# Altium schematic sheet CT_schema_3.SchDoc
size 372 x 317 mm
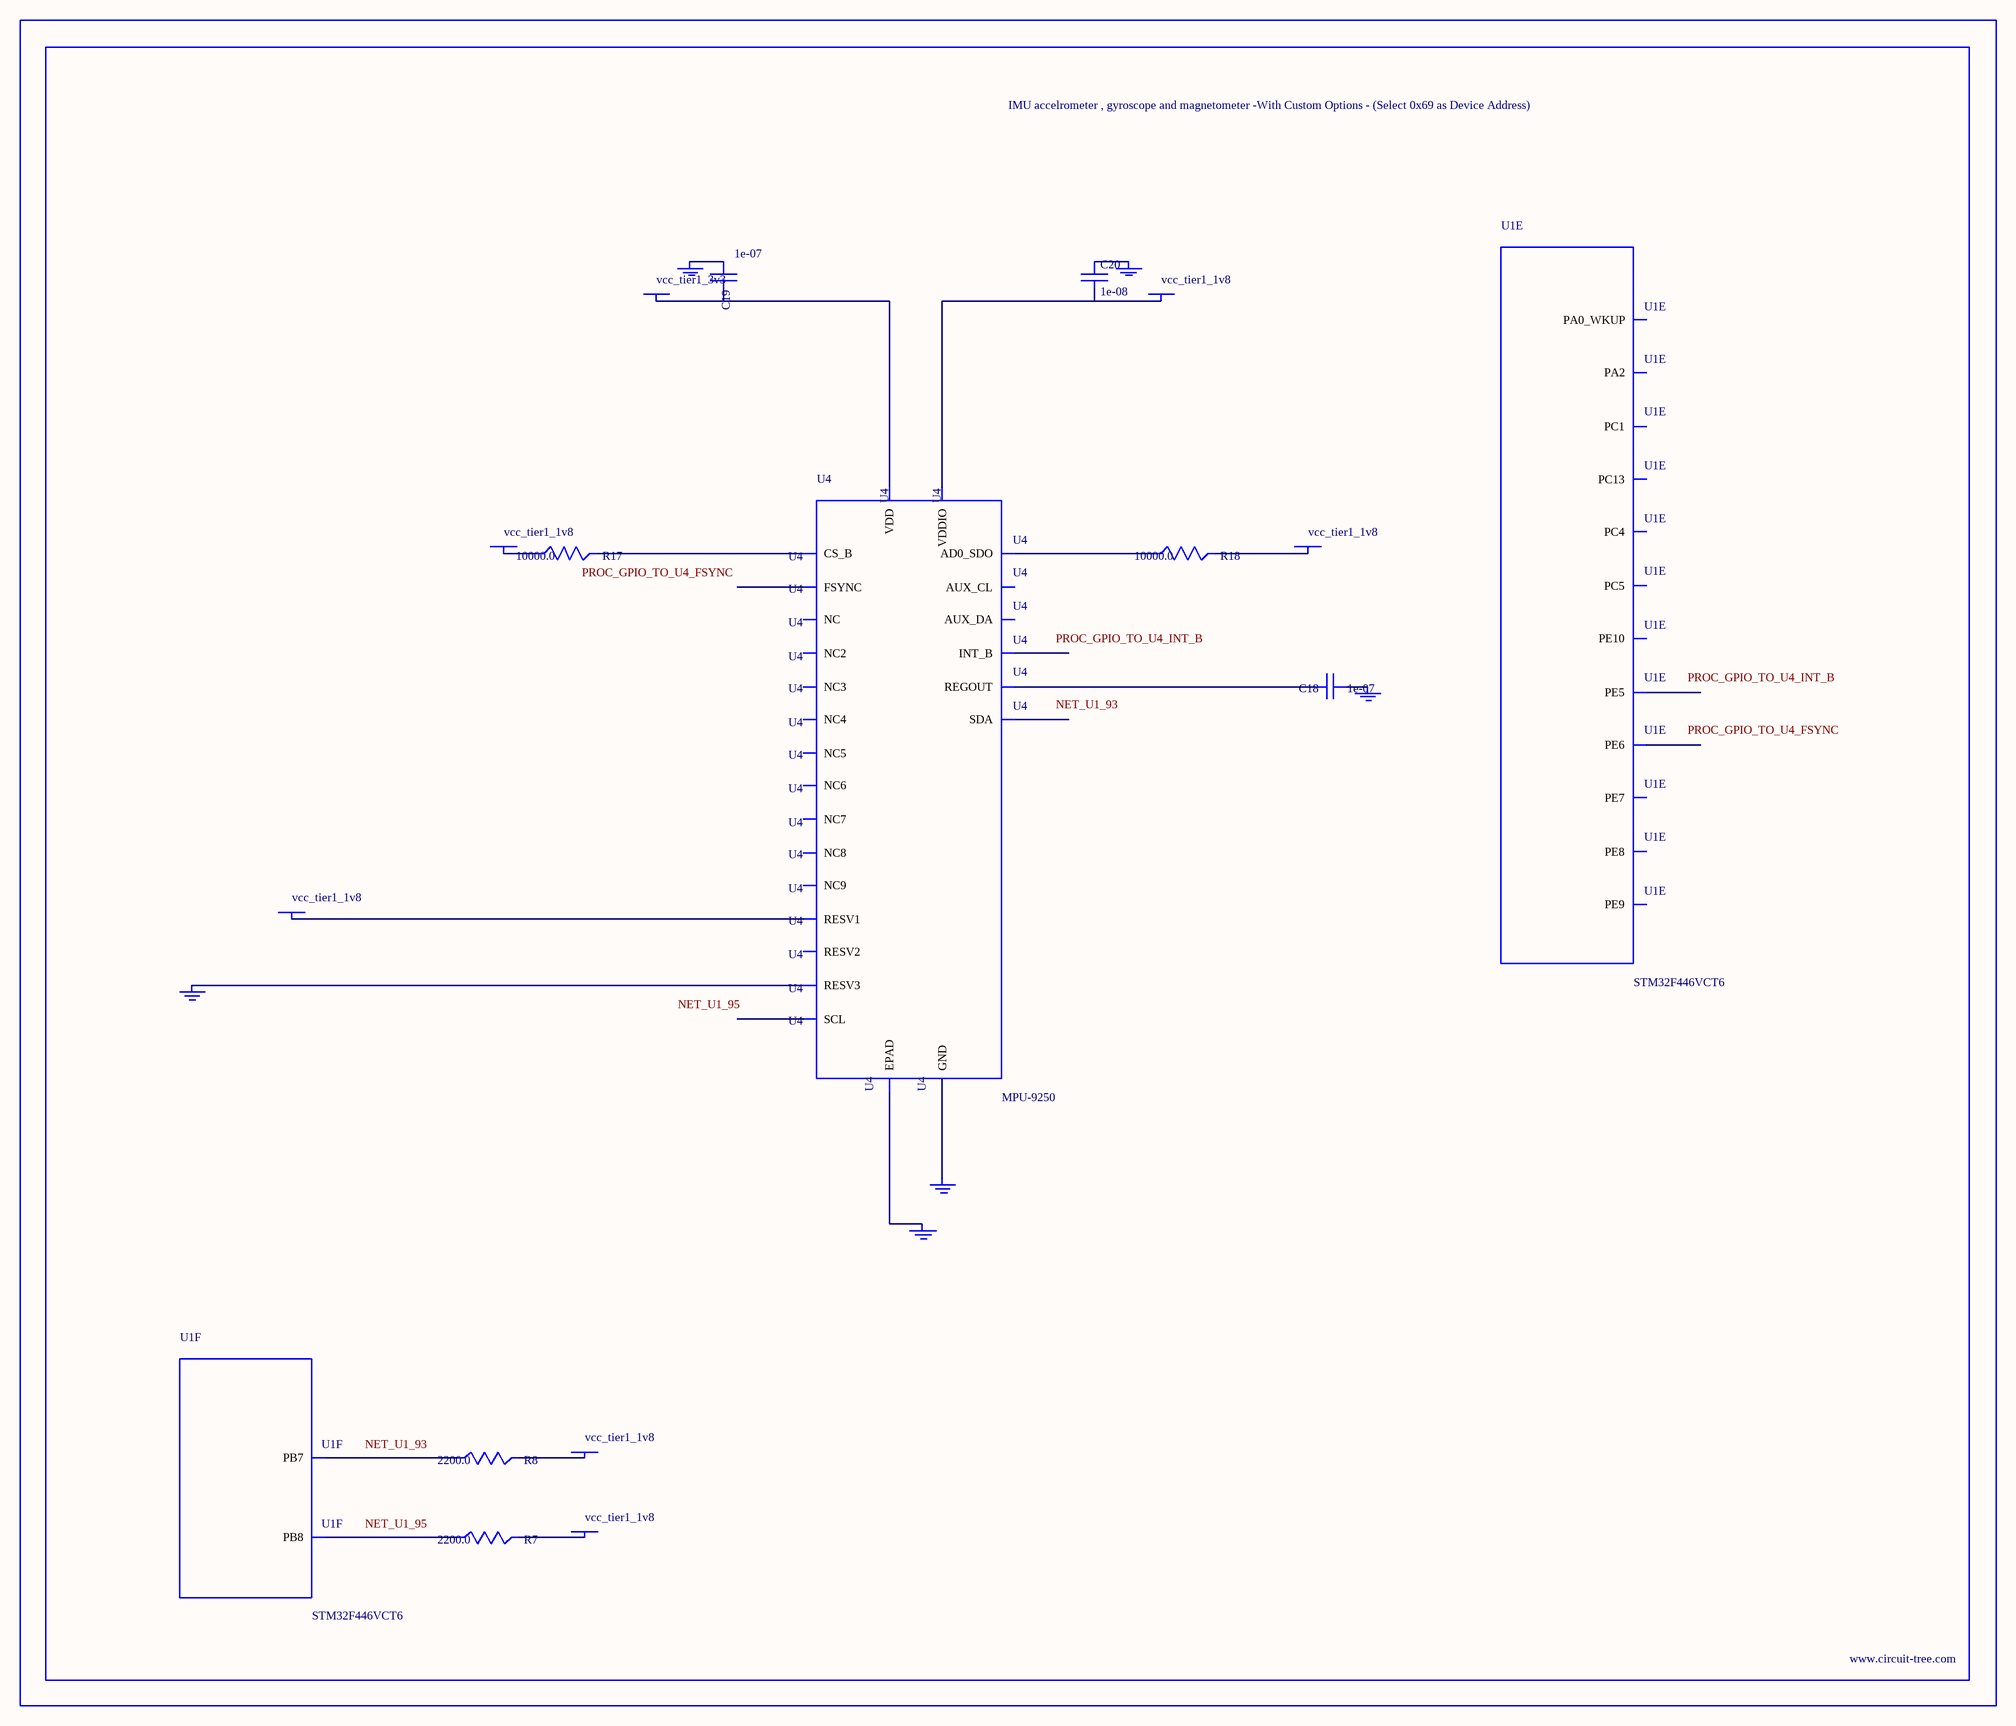
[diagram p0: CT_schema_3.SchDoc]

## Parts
BORDER2  (no value)
C18  1e-07  [C0402]
C19  1e-07  [C0402]
C20  1e-08  [C0402]
GND_INSTANCE_2_0  (no value)
GND_INSTANCE_2_1  (no value)
GND_INSTANCE_2_2  (no value)
GND_INSTANCE_2_3  (no value)
GND_INSTANCE_2_4  (no value)
GND_INSTANCE_2_5  (no value)
POWER_INSTANCE_2_0  vcc_tier1_1v8
POWER_INSTANCE_2_1  vcc_tier1_1v8
POWER_INSTANCE_2_2  vcc_tier1_1v8
POWER_INSTANCE_2_3  vcc_tier1_3v3
POWER_INSTANCE_2_4  vcc_tier1_1v8
POWER_INSTANCE_2_5  vcc_tier1_1v8
POWER_INSTANCE_2_6  vcc_tier1_1v8
R7  2200.0  [R0603]
R8  2200.0  [R0603]
R17  10000.0  [R0603]
R18  10000.0  [R0603]
U1  STM32F446VCT6  [LQFP100]  (parts E,F of 9)
U4  MPU-9250  [QFN24_2]

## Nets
NetC18_1: C18.1 GND_INSTANCE_2_1.0(GND)
NetC18_2: C18.2 U4.10(REGOUT)
NetC19_1: C19.1 GND_INSTANCE_2_2.0(GND)
NetC19_2: C19.2 POWER_INSTANCE_2_3.0(PWR) U4.13(VDD)
NetC20_1: C20.1 GND_INSTANCE_2_0.0(GND)
NetC20_2: C20.2 POWER_INSTANCE_2_1.0(PWR) U4.8(VDDIO)
NetGND_INSTANCE_2_3_0: GND_INSTANCE_2_3.0(GND) U4.20(RESV3)
NetGND_INSTANCE_2_4_0: GND_INSTANCE_2_4.0(GND) U4.25(EPAD)
NetGND_INSTANCE_2_5_0: GND_INSTANCE_2_5.0(GND) U4.18(GND)
NetPOWER_INSTANCE_2_0_0: POWER_INSTANCE_2_0.0(PWR) U4.1(RESV1)
NetPOWER_INSTANCE_2_2_0: POWER_INSTANCE_2_2.0(PWR) R18.2
NetPOWER_INSTANCE_2_4_0: POWER_INSTANCE_2_4.0(PWR) R17.1
NetPOWER_INSTANCE_2_5_0: POWER_INSTANCE_2_5.0(PWR) R8.2
NetPOWER_INSTANCE_2_6_0: POWER_INSTANCE_2_6.0(PWR) R7.2
NetR7_1: R7.1 U1.95(PB8)
NetR8_1: R8.1 U1.93(PB7)
NetR17_2: R17.2 U4.22(CS_B)
NetR18_1: R18.1 U4.9(AD0_SDO)

Not connected (* = marked no-connect by the designer): U1 4(PE5) 5(PE6) 7(PC13) 16(PC1) 23(PA0_WKUP) 25(PA2) 33(PC4) 34(PC5) 38(PE7) 39(PE8) 40(PE9) 41(PE10); U4 2(NC) 3(NC2) 4(NC3) 5(NC4) 6(NC5) 7(AUX_CL) 11(FSYNC) 12(INT_B) 14(NC6) 15(NC7) 16(NC8) 17(NC9) 19(RESV2) 21(AUX_DA) 23(SCL) 24(SDA)

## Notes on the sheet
- Labels drawn without touching a wire or pin: NET_U1_93, NET_U1_95, PROC_GPIO_TO_U4_FSYNC, PROC_GPIO_TO_U4_INT_B

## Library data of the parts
BORDER2 = BORDER_PAGE2
C18 C19 = C0402C104K3RACTU
C20 = C0402C103K3RAC
GND_INSTANCE_2_0-GND_INSTANCE_2_5 = GND
POWER_INSTANCE_2_0-POWER_INSTANCE_2_6 = PWR
R7 R8 = RC0603JR-072K2L
R17 R18 = RC0603JR-0710KL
